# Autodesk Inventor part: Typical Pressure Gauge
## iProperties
Company: WSRC - Nonproliferation Technologies Section
Title: Typical Pressure Gauge
Author: Mike Maxwell
Revision Number: 0
Shininess: 41.0
PropertySet Name: _Private Model Information
Created: 2001-04
Part Number: Gauge Ashcroft 1279LC
Material: Phenolic
Document SubType Name: Modeling
Designer: Mike Maxwell
Engineer: Mike Maxwell
Project: Standard Instrumentation
Description: Typical Duragauge Pressure Gauge
Vendor: Ashcroft
Control State: 0
Master: False
Checked Out: False
PropertySet Name: Design Tracking Control
Density: 1.38
Volumn: 163.0602976502082
Area: 386.5623854208644
PropertySet Name: Model Information
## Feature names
1. Extrusion1
2. Loft1
3. Loft2
4. Loft4
5. Loft5
6. Hole1
7. Hole2
8. Hole3
9. Extrusion2
10. Hole4
11. Extrusion3
12. Extrusion4
13. Extrusion5
14. Circular Pattern1
15. Extrusion9
16. Hole5
